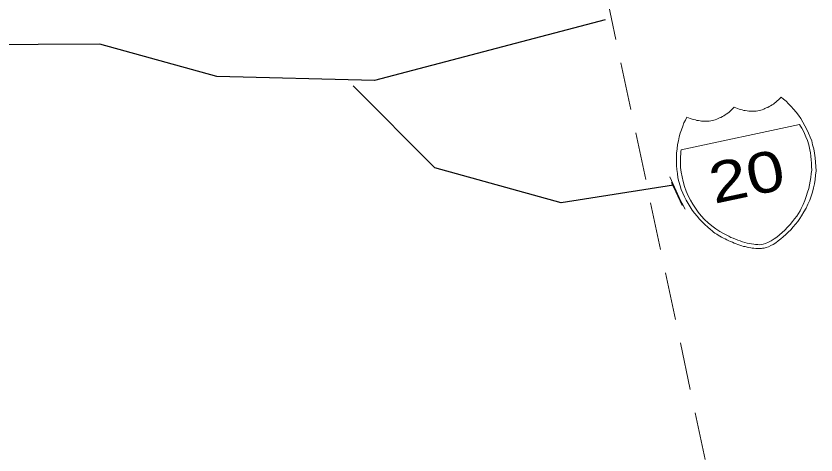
# Model space of a CAD drawing. Extents: x 2357218 to 2371708, y 6973728 to 6980157.
# Drawn here: x 2357307.6 to 2357408.3, y 6974565 to 6974620.2 of the extents above; entities that cross this region are included whole.
import ezdxf

# ---------------------------------------------------------------- set-up
doc = ezdxf.new("R2010")
doc.units = 0
doc.header["$LTSCALE"] = 2
doc.linetypes.add('MEDIUM_DASHED', pattern=[4.5, 3, -1.5])
doc.layers.add('62', color=7, linetype='Continuous', lineweight=13)
doc.layers.add('63', color=7, linetype='Continuous', lineweight=13)

msp = doc.modelspace()

# ---------------------------------------------------------------- linework, layer by layer
at = {"layer": '62', "linetype": 'MEDIUM_DASHED'}
msp.add_line((2357366.864, 6974693.567), (2357405.498, 6974511.924), dxfattribs=at)
at = {"layer": '62'}
for p, q in [((2357389.882, 6974599.998), (2357391.051, 6974597.419)), ((2357390.102, 6974599.286), (2357391.424, 6974596.416)), ((2357390.151, 6974599.045), (2357391.822, 6974595.95))]:
    msp.add_line(p, q, dxfattribs=at)
at = {"layer": '62', "lineweight": 25}
for points in [[(2357381.721, 6974619.775), (2357352.675, 6974612.153), (2357332.858, 6974612.633), (2357318.116, 6974616.722), (2357302.539, 6974616.63), (2357295.874, 6974613.673)], [(2357390.356, 6974598.95), (2357376.195, 6974596.744), (2357360.278, 6974601.163), (2357350.015, 6974611.472)]]:
    msp.add_lwpolyline(points, dxfattribs=at)
at = {"layer": '62'}
for points in [[(2357398.798, 6974608.475), (2357398.993, 6974608.424), (2357399.209, 6974608.378), (2357399.377, 6974608.346), (2357399.596, 6974608.3), (2357399.803, 6974608.298), (2357399.993, 6974608.268), (2357400.173, 6974608.285), (2357400.378, 6974608.282), (2357400.566, 6974608.274), (2357400.766, 6974608.294), (2357400.944, 6974608.332), (2357401.144, 6974608.376), (2357401.32, 6974608.414), (2357401.496, 6974608.451), (2357401.712, 6974608.52), (2357401.856, 6974608.595), (2357402.022, 6974608.678), (2357402.217, 6974608.742), (2357402.401, 6974608.85), (2357402.569, 6974608.932), (2357402.746, 6974609.061), (2357402.909, 6974609.164), (2357403.064, 6974609.289), (2357403.225, 6974609.416), (2357403.375, 6974609.564), (2357403.55, 6974609.716), (2357403.726, 6974609.87), (2357403.874, 6974610.038), (2357404.203, 6974609.787), (2357404.51, 6974609.528), (2357404.832, 6974609.205), (2357405.154, 6974608.883), (2357405.458, 6974608.531), (2357405.767, 6974608.161), (2357406.059, 6974607.763), (2357406.35, 6974607.365), (2357406.633, 6974606.896), (2357406.889, 6974606.445), (2357407.127, 6974605.987), (2357407.344, 6974605.506), (2357407.54, 6974605.017), (2357407.735, 6974604.531), (2357407.86, 6974604.051), (2357408.017, 6974603.533), (2357408.084, 6974602.994), (2357408.184, 6974602.418), (2357408.209, 6974601.869), (2357408.254, 6974601.329), (2357408.28, 6974600.782), (2357408.215, 6974600.216), (2357408.163, 6974599.699), (2357408.095, 6974599.156), (2357407.979, 6974598.623), (2357407.839, 6974598.09), (2357407.67, 6974597.594), (2357407.503, 6974597.074), (2357407.267, 6974596.564), (2357407.025, 6974596.077), (2357406.758, 6974595.605), (2357406.449, 6974595.103), (2357406.225, 6974594.755), (2357405.981, 6974594.382), (2357405.685, 6974594.043), (2357405.412, 6974593.709), (2357405.093, 6974593.366), (2357404.769, 6974593.043), (2357404.466, 6974592.748), (2357404.159, 6974592.451), (2357403.843, 6974592.202), (2357403.529, 6974591.951), (2357403.209, 6974591.722), (2357402.887, 6974591.517), (2357402.592, 6974591.384), (2357402.302, 6974591.229), (2357402.004, 6974591.121), (2357401.747, 6974591.043)], [(2357401.747, 6974591.043), (2357401.562, 6974591.026), (2357401.409, 6974590.994), (2357401.224, 6974591.001), (2357401.067, 6974590.991), (2357400.879, 6974590.998), (2357400.694, 6974591.003), (2357400.461, 6974591.023), (2357400.249, 6974591.048), (2357400.055, 6974591.096), (2357399.836, 6974591.142), (2357399.598, 6974591.185), (2357399.382, 6974591.232), (2357399.142, 6974591.273), (2357398.945, 6974591.343), (2357398.696, 6974591.429), (2357398.451, 6974591.494), (2357398.225, 6974591.583), (2357397.972, 6974591.69), (2357397.748, 6974591.78), (2357397.523, 6974591.869), (2357397.29, 6974591.981), (2357397.06, 6974592.095), (2357396.828, 6974592.205), (2357396.619, 6974592.321), (2357396.388, 6974592.435), (2357396.179, 6974592.552), (2357395.966, 6974592.69), (2357395.779, 6974592.811), (2357395.544, 6974592.945), (2357395.357, 6974593.065), (2357395.188, 6974593.215), (2357394.991, 6974593.38), (2357394.65, 6974593.675), (2357394.282, 6974594.012), (2357393.956, 6974594.355), (2357393.629, 6974594.699), (2357393.299, 6974595.067), (2357392.99, 6974595.437), (2357392.703, 6974595.815), (2357392.45, 6974596.244), (2357392.181, 6974596.647), (2357391.949, 6974597.08), (2357391.741, 6974597.52), (2357391.534, 6974597.959), (2357391.321, 6974598.42), (2357391.174, 6974598.892), (2357391.016, 6974599.413), (2357390.894, 6974599.892), (2357390.824, 6974600.431), (2357390.766, 6974600.924), (2357390.723, 6974601.444), (2357390.706, 6974601.969), (2357390.706, 6974602.497), (2357390.734, 6974603.011), (2357390.786, 6974603.527), (2357390.834, 6974604.067), (2357390.96, 6974604.552), (2357391.066, 6974605.036), (2357391.196, 6974605.499), (2357391.331, 6974605.945), (2357391.513, 6974606.374), (2357391.633, 6974606.792), (2357391.832, 6974607.156), (2357392.03, 6974607.521), (2357392.234, 6974607.427), (2357392.457, 6974607.358), (2357392.678, 6974607.291), (2357392.88, 6974607.217), (2357393.094, 6974607.171), (2357393.289, 6974607.12), (2357393.501, 6974607.095), (2357393.697, 6974607.046), (2357393.881, 6974607.039), (2357394.071, 6974607.01), (2357394.275, 6974607.031), (2357394.461, 6974607.023), (2357394.691, 6974607.027), (2357394.848, 6974607.038), (2357395.024, 6974607.076), (2357395.246, 6974607.121), (2357395.421, 6974607.16), (2357395.596, 6974607.195), (2357395.791, 6974607.259), (2357395.957, 6974607.342), (2357396.122, 6974607.422), (2357396.295, 6974607.483), (2357396.503, 6974607.595), (2357396.669, 6974607.677), (2357396.824, 6974607.803), (2357396.987, 6974607.905), (2357397.165, 6974608.036), (2357397.346, 6974608.166), (2357397.499, 6974608.315), (2357397.651, 6974608.463), (2357397.804, 6974608.609), (2357397.974, 6974608.784), (2357398.178, 6974608.689), (2357398.377, 6974608.617), (2357398.598, 6974608.548), (2357398.798, 6974608.475)]]:
    msp.add_lwpolyline(points, dxfattribs=at)
msp.add_lwpolyline([(2357406.214, 6974606.598), (2357391.313, 6974603.431), (2357391.272, 6974603.193), (2357391.244, 6974602.888), (2357391.222, 6974602.561), (2357391.22, 6974602.146), (2357391.202, 6974601.682), (2357391.217, 6974601.181), (2357391.291, 6974600.62), (2357391.42, 6974600.004), (2357391.546, 6974599.409), (2357391.722, 6974598.804), (2357391.939, 6974598.206), (2357392.2, 6974597.64), (2357392.479, 6974597.078), (2357392.768, 6974596.586), (2357393.089, 6974596.059), (2357393.465, 6974595.585), (2357393.839, 6974595.114), (2357394.235, 6974594.668), (2357394.695, 6974594.236), (2357395.145, 6974593.848), (2357395.66, 6974593.477), (2357396.193, 6974593.13), (2357396.718, 6974592.826), (2357397.287, 6974592.533), (2357397.549, 6974592.381), (2357397.845, 6974592.285), (2357398.126, 6974592.159), (2357398.444, 6974592.065), (2357398.719, 6974591.964), (2357399.021, 6974591.843), (2357399.314, 6974591.769), (2357399.605, 6974591.692), (2357399.892, 6974591.639), (2357400.158, 6974591.581), (2357400.448, 6974591.526), (2357400.684, 6974591.485), (2357400.957, 6974591.497), (2357401.19, 6974591.476), (2357401.416, 6974591.5), (2357401.643, 6974591.528), (2357401.94, 6974591.635), (2357402.301, 6974591.782), (2357402.63, 6974591.966), (2357402.993, 6974592.203), (2357403.338, 6974592.416), (2357403.686, 6974592.721), (2357404.015, 6974593.021), (2357404.366, 6974593.323), (2357404.706, 6974593.674), (2357405.021, 6974594.039), (2357405.315, 6974594.377), (2357405.585, 6974594.735), (2357405.859, 6974595.069), (2357406.089, 6974595.393), (2357406.292, 6974595.737), (2357406.417, 6974596.016), (2357406.671, 6974596.553), (2357406.863, 6974597.054), (2357407.055, 6974597.553), (2357407.221, 6974598.071), (2357407.377, 6974598.541), (2357407.48, 6974599.026), (2357407.566, 6974599.479), (2357407.629, 6974599.953), (2357407.688, 6974600.425), (2357407.735, 6974600.848), (2357407.729, 6974601.309), (2357407.706, 6974601.742), (2357407.684, 6974602.174), (2357407.638, 6974602.601), (2357407.573, 6974603.022), (2357407.489, 6974603.42), (2357407.358, 6974604.036), (2357407.196, 6974604.578), (2357407.005, 6974605.041), (2357406.845, 6974605.467), (2357406.651, 6974605.84), (2357406.476, 6974606.125), (2357406.327, 6974606.394)], close=True, dxfattribs=at)
at = {"layer": '63', "linetype": 'MEDIUM_DASHED'}
msp.add_line((2357366.864, 6974693.567), (2357405.498, 6974511.924), dxfattribs=at)
at = {"layer": '63'}
for p, q in [((2357389.882, 6974599.998), (2357391.051, 6974597.419)), ((2357390.102, 6974599.286), (2357391.424, 6974596.416)), ((2357390.151, 6974599.045), (2357391.822, 6974595.95))]:
    msp.add_line(p, q, dxfattribs=at)
at = {"layer": '63', "lineweight": 25}
for points in [[(2357381.721, 6974619.775), (2357352.675, 6974612.153), (2357332.858, 6974612.633), (2357318.116, 6974616.722), (2357302.539, 6974616.63), (2357295.874, 6974613.673)], [(2357390.356, 6974598.95), (2357376.195, 6974596.744), (2357360.278, 6974601.163), (2357350.015, 6974611.472)]]:
    msp.add_lwpolyline(points, dxfattribs=at)
at = {"layer": '63'}
for points in [[(2357398.798, 6974608.475), (2357398.993, 6974608.424), (2357399.209, 6974608.378), (2357399.377, 6974608.346), (2357399.596, 6974608.3), (2357399.803, 6974608.298), (2357399.993, 6974608.268), (2357400.173, 6974608.285), (2357400.378, 6974608.282), (2357400.566, 6974608.274), (2357400.766, 6974608.294), (2357400.944, 6974608.332), (2357401.144, 6974608.376), (2357401.32, 6974608.414), (2357401.496, 6974608.451), (2357401.712, 6974608.52), (2357401.856, 6974608.595), (2357402.022, 6974608.678), (2357402.217, 6974608.742), (2357402.401, 6974608.85), (2357402.569, 6974608.932), (2357402.746, 6974609.061), (2357402.909, 6974609.164), (2357403.064, 6974609.289), (2357403.225, 6974609.416), (2357403.375, 6974609.564), (2357403.55, 6974609.716), (2357403.726, 6974609.87), (2357403.874, 6974610.038), (2357404.203, 6974609.787), (2357404.51, 6974609.528), (2357404.832, 6974609.205), (2357405.154, 6974608.883), (2357405.458, 6974608.531), (2357405.767, 6974608.161), (2357406.059, 6974607.763), (2357406.35, 6974607.365), (2357406.633, 6974606.896), (2357406.889, 6974606.445), (2357407.127, 6974605.987), (2357407.344, 6974605.506), (2357407.54, 6974605.017), (2357407.735, 6974604.531), (2357407.86, 6974604.051), (2357408.017, 6974603.533), (2357408.084, 6974602.994), (2357408.184, 6974602.418), (2357408.209, 6974601.869), (2357408.254, 6974601.329), (2357408.28, 6974600.782), (2357408.215, 6974600.216), (2357408.163, 6974599.699), (2357408.095, 6974599.156), (2357407.979, 6974598.623), (2357407.839, 6974598.09), (2357407.67, 6974597.594), (2357407.503, 6974597.074), (2357407.267, 6974596.564), (2357407.025, 6974596.077), (2357406.758, 6974595.605), (2357406.449, 6974595.103), (2357406.225, 6974594.755), (2357405.981, 6974594.382), (2357405.685, 6974594.043), (2357405.412, 6974593.709), (2357405.093, 6974593.366), (2357404.769, 6974593.043), (2357404.466, 6974592.748), (2357404.159, 6974592.451), (2357403.843, 6974592.202), (2357403.529, 6974591.951), (2357403.209, 6974591.722), (2357402.887, 6974591.517), (2357402.592, 6974591.384), (2357402.302, 6974591.229), (2357402.004, 6974591.121), (2357401.747, 6974591.043)], [(2357401.747, 6974591.043), (2357401.562, 6974591.026), (2357401.409, 6974590.994), (2357401.224, 6974591.001), (2357401.067, 6974590.991), (2357400.879, 6974590.998), (2357400.694, 6974591.003), (2357400.461, 6974591.023), (2357400.249, 6974591.048), (2357400.055, 6974591.096), (2357399.836, 6974591.142), (2357399.598, 6974591.185), (2357399.382, 6974591.232), (2357399.142, 6974591.273), (2357398.945, 6974591.343), (2357398.696, 6974591.429), (2357398.451, 6974591.494), (2357398.225, 6974591.583), (2357397.972, 6974591.69), (2357397.748, 6974591.78), (2357397.523, 6974591.869), (2357397.29, 6974591.981), (2357397.06, 6974592.095), (2357396.828, 6974592.205), (2357396.619, 6974592.321), (2357396.388, 6974592.435), (2357396.179, 6974592.552), (2357395.966, 6974592.69), (2357395.779, 6974592.811), (2357395.544, 6974592.945), (2357395.357, 6974593.065), (2357395.188, 6974593.215), (2357394.991, 6974593.38), (2357394.65, 6974593.675), (2357394.282, 6974594.012), (2357393.956, 6974594.355), (2357393.629, 6974594.699), (2357393.299, 6974595.067), (2357392.99, 6974595.437), (2357392.703, 6974595.815), (2357392.45, 6974596.244), (2357392.181, 6974596.647), (2357391.949, 6974597.08), (2357391.741, 6974597.52), (2357391.534, 6974597.959), (2357391.321, 6974598.42), (2357391.174, 6974598.892), (2357391.016, 6974599.413), (2357390.894, 6974599.892), (2357390.824, 6974600.431), (2357390.766, 6974600.924), (2357390.723, 6974601.444), (2357390.706, 6974601.969), (2357390.706, 6974602.497), (2357390.734, 6974603.011), (2357390.786, 6974603.527), (2357390.834, 6974604.067), (2357390.96, 6974604.552), (2357391.066, 6974605.036), (2357391.196, 6974605.499), (2357391.331, 6974605.945), (2357391.513, 6974606.374), (2357391.633, 6974606.792), (2357391.832, 6974607.156), (2357392.03, 6974607.521), (2357392.234, 6974607.427), (2357392.457, 6974607.358), (2357392.678, 6974607.291), (2357392.88, 6974607.217), (2357393.094, 6974607.171), (2357393.289, 6974607.12), (2357393.501, 6974607.095), (2357393.697, 6974607.046), (2357393.881, 6974607.039), (2357394.071, 6974607.01), (2357394.275, 6974607.031), (2357394.461, 6974607.023), (2357394.691, 6974607.027), (2357394.848, 6974607.038), (2357395.024, 6974607.076), (2357395.246, 6974607.121), (2357395.421, 6974607.16), (2357395.596, 6974607.195), (2357395.791, 6974607.259), (2357395.957, 6974607.342), (2357396.122, 6974607.422), (2357396.295, 6974607.483), (2357396.503, 6974607.595), (2357396.669, 6974607.677), (2357396.824, 6974607.803), (2357396.987, 6974607.905), (2357397.165, 6974608.036), (2357397.346, 6974608.166), (2357397.499, 6974608.315), (2357397.651, 6974608.463), (2357397.804, 6974608.609), (2357397.974, 6974608.784), (2357398.178, 6974608.689), (2357398.377, 6974608.617), (2357398.598, 6974608.548), (2357398.798, 6974608.475)]]:
    msp.add_lwpolyline(points, dxfattribs=at)
msp.add_lwpolyline([(2357406.214, 6974606.598), (2357391.313, 6974603.431), (2357391.272, 6974603.193), (2357391.244, 6974602.888), (2357391.222, 6974602.561), (2357391.22, 6974602.146), (2357391.202, 6974601.682), (2357391.217, 6974601.181), (2357391.291, 6974600.62), (2357391.42, 6974600.004), (2357391.546, 6974599.409), (2357391.722, 6974598.804), (2357391.939, 6974598.206), (2357392.2, 6974597.64), (2357392.479, 6974597.078), (2357392.768, 6974596.586), (2357393.089, 6974596.059), (2357393.465, 6974595.585), (2357393.839, 6974595.114), (2357394.235, 6974594.668), (2357394.695, 6974594.236), (2357395.145, 6974593.848), (2357395.66, 6974593.477), (2357396.193, 6974593.13), (2357396.718, 6974592.826), (2357397.287, 6974592.533), (2357397.549, 6974592.381), (2357397.845, 6974592.285), (2357398.126, 6974592.159), (2357398.444, 6974592.065), (2357398.719, 6974591.964), (2357399.021, 6974591.843), (2357399.314, 6974591.769), (2357399.605, 6974591.692), (2357399.892, 6974591.639), (2357400.158, 6974591.581), (2357400.448, 6974591.526), (2357400.684, 6974591.485), (2357400.957, 6974591.497), (2357401.19, 6974591.476), (2357401.416, 6974591.5), (2357401.643, 6974591.528), (2357401.94, 6974591.635), (2357402.301, 6974591.782), (2357402.63, 6974591.966), (2357402.993, 6974592.203), (2357403.338, 6974592.416), (2357403.686, 6974592.721), (2357404.015, 6974593.021), (2357404.366, 6974593.323), (2357404.706, 6974593.674), (2357405.021, 6974594.039), (2357405.315, 6974594.377), (2357405.585, 6974594.735), (2357405.859, 6974595.069), (2357406.089, 6974595.393), (2357406.292, 6974595.737), (2357406.417, 6974596.016), (2357406.671, 6974596.553), (2357406.863, 6974597.054), (2357407.055, 6974597.553), (2357407.221, 6974598.071), (2357407.377, 6974598.541), (2357407.48, 6974599.026), (2357407.566, 6974599.479), (2357407.629, 6974599.953), (2357407.688, 6974600.425), (2357407.735, 6974600.848), (2357407.729, 6974601.309), (2357407.706, 6974601.742), (2357407.684, 6974602.174), (2357407.638, 6974602.601), (2357407.573, 6974603.022), (2357407.489, 6974603.42), (2357407.358, 6974604.036), (2357407.196, 6974604.578), (2357407.005, 6974605.041), (2357406.845, 6974605.467), (2357406.651, 6974605.84), (2357406.476, 6974606.125), (2357406.327, 6974606.394)], close=True, dxfattribs=at)

# ---------------------------------------------------------------- texts
at = {"layer": '62', "width": 1.25}
msp.add_text('20', height=5.099, rotation=12, dxfattribs=at).set_placement((2357395.454, 6974596.607))
at = {"layer": '63', "width": 1.25}
msp.add_text('20', height=5.099, rotation=12, dxfattribs=at).set_placement((2357395.454, 6974596.607))

doc.saveas('drawing.dxf')
